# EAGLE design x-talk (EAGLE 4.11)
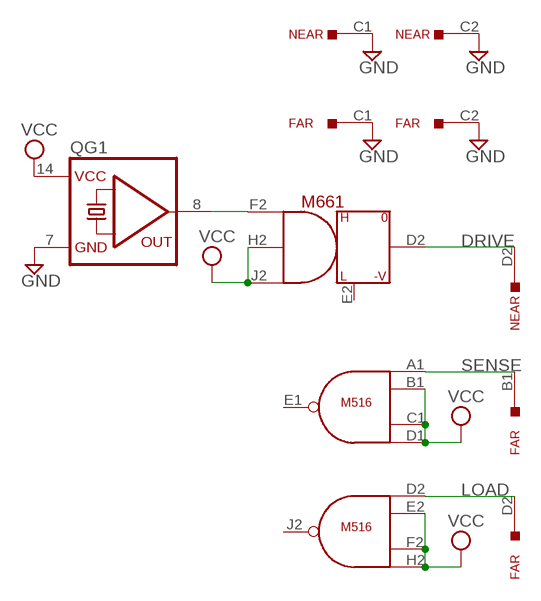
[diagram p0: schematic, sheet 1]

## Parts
FAR  M916  [H807]
M516  M117  [H807]
M661  M651  [H807]
NEAR  M916  [H807]
QG1  QG5860  [DIL14S]

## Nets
DRIVE: M661.D2(OUT) NEAR.D2
GND: FAR.C1 FAR.C2 NEAR.C1 NEAR.C2 QG1.7(GND)
LOAD: FAR.D2 M516.D2(IN1)
N$1: M661.F2(IN1) QG1.8(OUT)
SENSE: FAR.B1 M516.A1(IN1)
VCC: M516.B1(IN2) M516.C1(IN3) M516.D1(IN4) M516.E2(IN2) M516.F2(IN3) M516.H2(IN4) M661.H2(IN2) M661.J2(IN3) QG1.14(VCC)
Unconnected: FAR.A1 FAR.A2 FAR.B2 FAR.D1 FAR.E1 FAR.E2 FAR.F1 FAR.F2 FAR.H1 FAR.H2 FAR.J1 FAR.J2 FAR.K1 FAR.K2 FAR.L1 FAR.L2 FAR.M1 FAR.M2 FAR.N1 FAR.N2 FAR.P1 FAR.P2 FAR.R1 FAR.R2 FAR.S1 FAR.S2 FAR.T1 FAR.T2 FAR.U1 FAR.U2 FAR.V1 FAR.V2 M516.E1(OUT) M516.F1(IN1) M516.H1(IN2) M516.J1(IN3) M516.J2(OUT) M516.K1(IN4) M516.K2(IN1) M516.L1(OUT) M516.L2(IN2) M516.M1(IN1) M516.M2(IN3) M516.N1(IN2) M516.N2(IN4) M516.P1(IN3) M516.P2(OUT) M516.R1(IN4) M516.R2(IN1) M516.S1(OUT) M516.S2(IN2) M516.T2(IN3) M516.U1 M516.U2(IN4) M516.V1 M516.V2(OUT) M661.E2(SLOW) M661.K2(OUT) M661.L2(SLOW) M661.M2(IN1) M661.N2(IN2) M661.P2(IN3) M661.R2(SLOW) M661.S2(OUT) M661.T2(IN1) M661.U2(IN2) M661.V2(IN3) NEAR.A1 NEAR.A2 NEAR.B1 NEAR.B2 NEAR.D1 NEAR.E1 NEAR.E2 NEAR.F1 NEAR.F2 NEAR.H1 NEAR.H2 NEAR.J1 NEAR.J2 NEAR.K1 NEAR.K2 NEAR.L1 NEAR.L2 NEAR.M1 NEAR.M2 NEAR.N1 NEAR.N2 NEAR.P1 NEAR.P2 NEAR.R1 NEAR.R2 NEAR.S1 NEAR.S2 NEAR.T1 NEAR.T2 NEAR.U1 NEAR.U2 NEAR.V1 NEAR.V2

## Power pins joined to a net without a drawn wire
-15V: M661.B2(-15V)
GND: M516.C2(GND) M516.T1(GND) M661.C2(GND)
VCC: M516.A2(VCC) M661.A2(VCC)

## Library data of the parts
FAR NEAR = dec-m:M916: Simple 36 pin connector/wire cable
M516 = dec-m:M117: 6 4-input NAND Gates
M661 = dec-m:M651: M651 - Negative Output Converter
QG1 = crystal:QG5860: CRYSTAL RESONATOR

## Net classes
0 default: width 0.508 mm

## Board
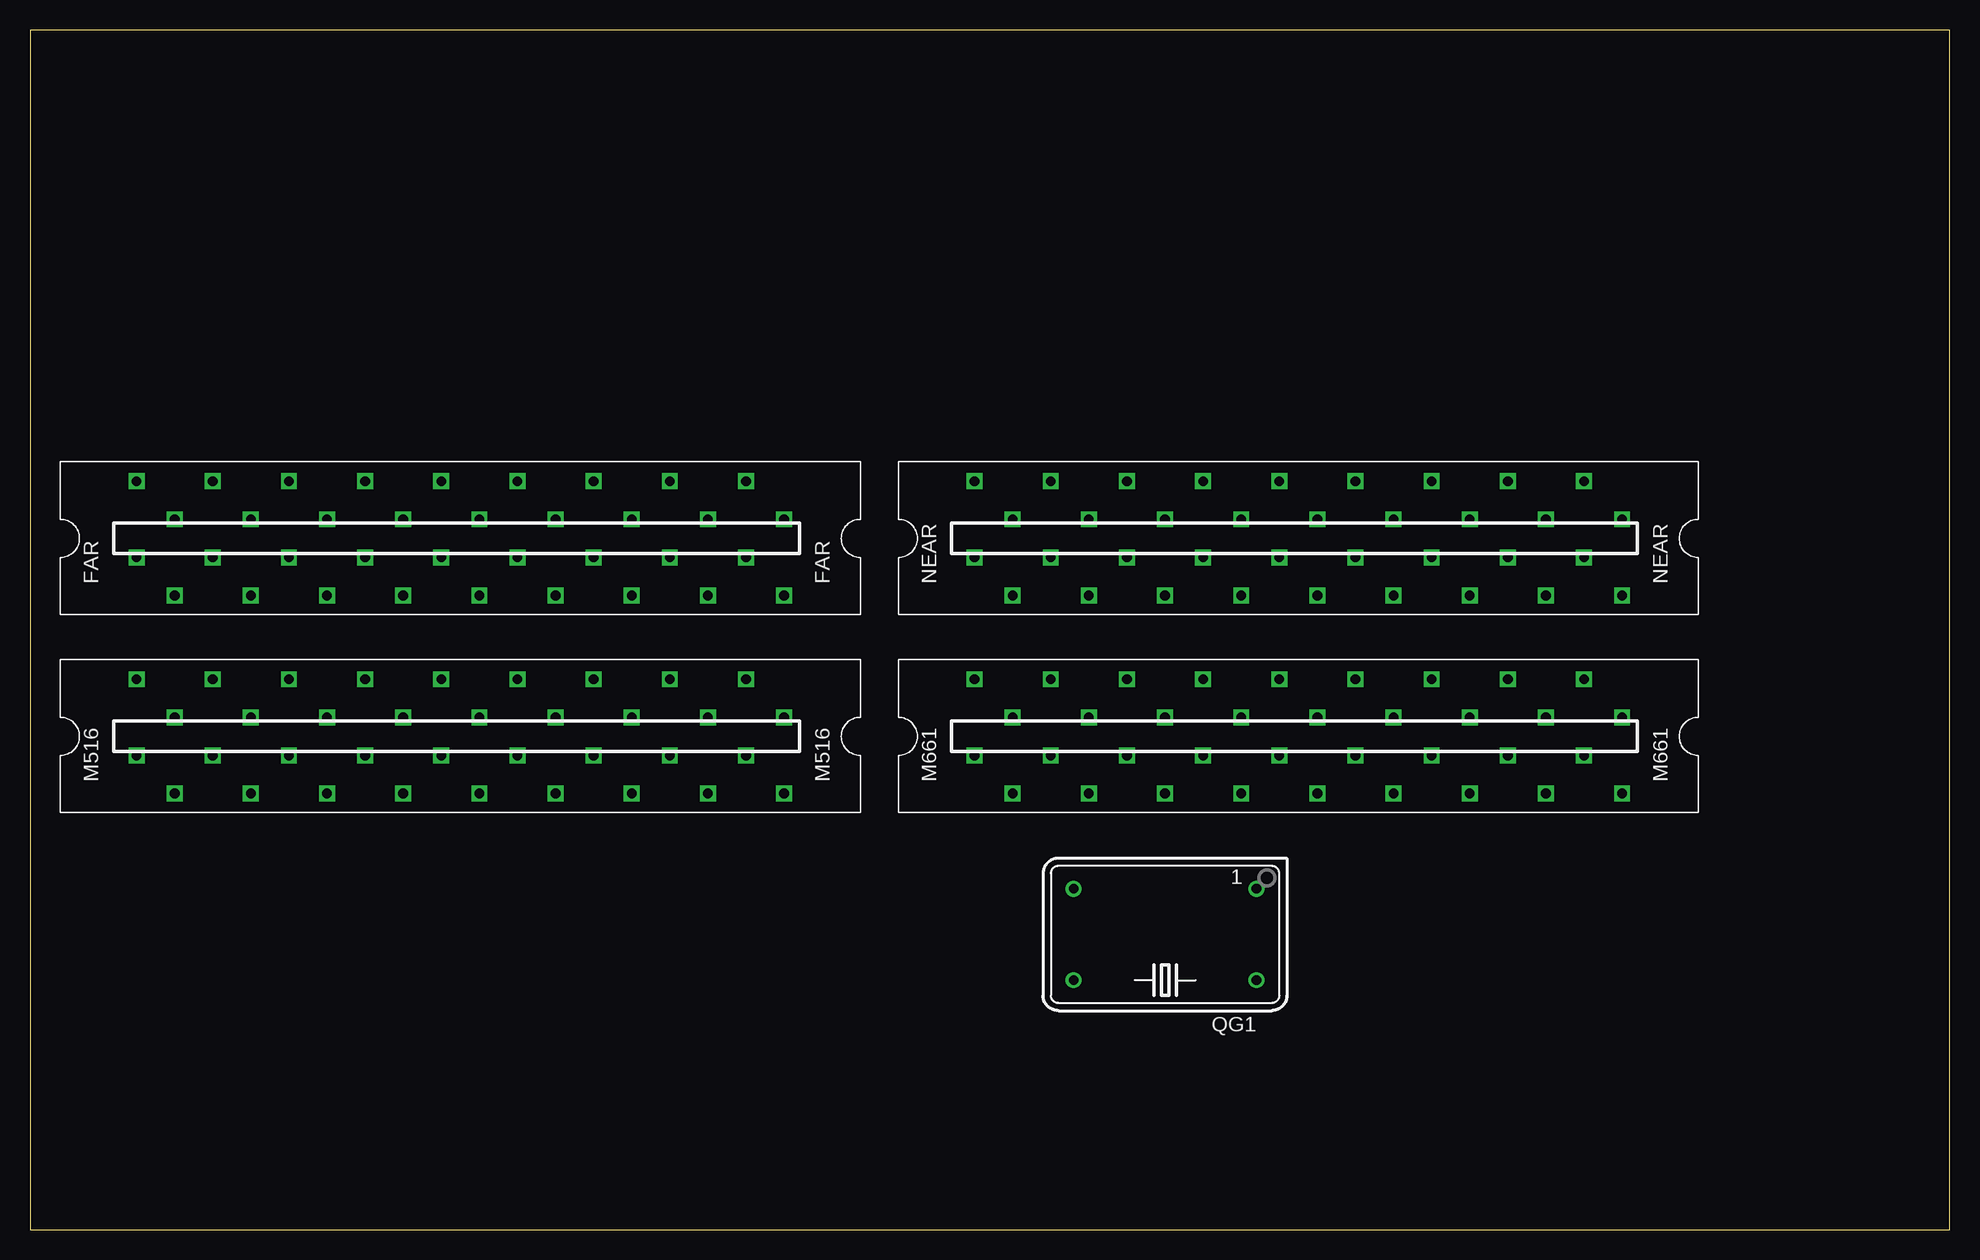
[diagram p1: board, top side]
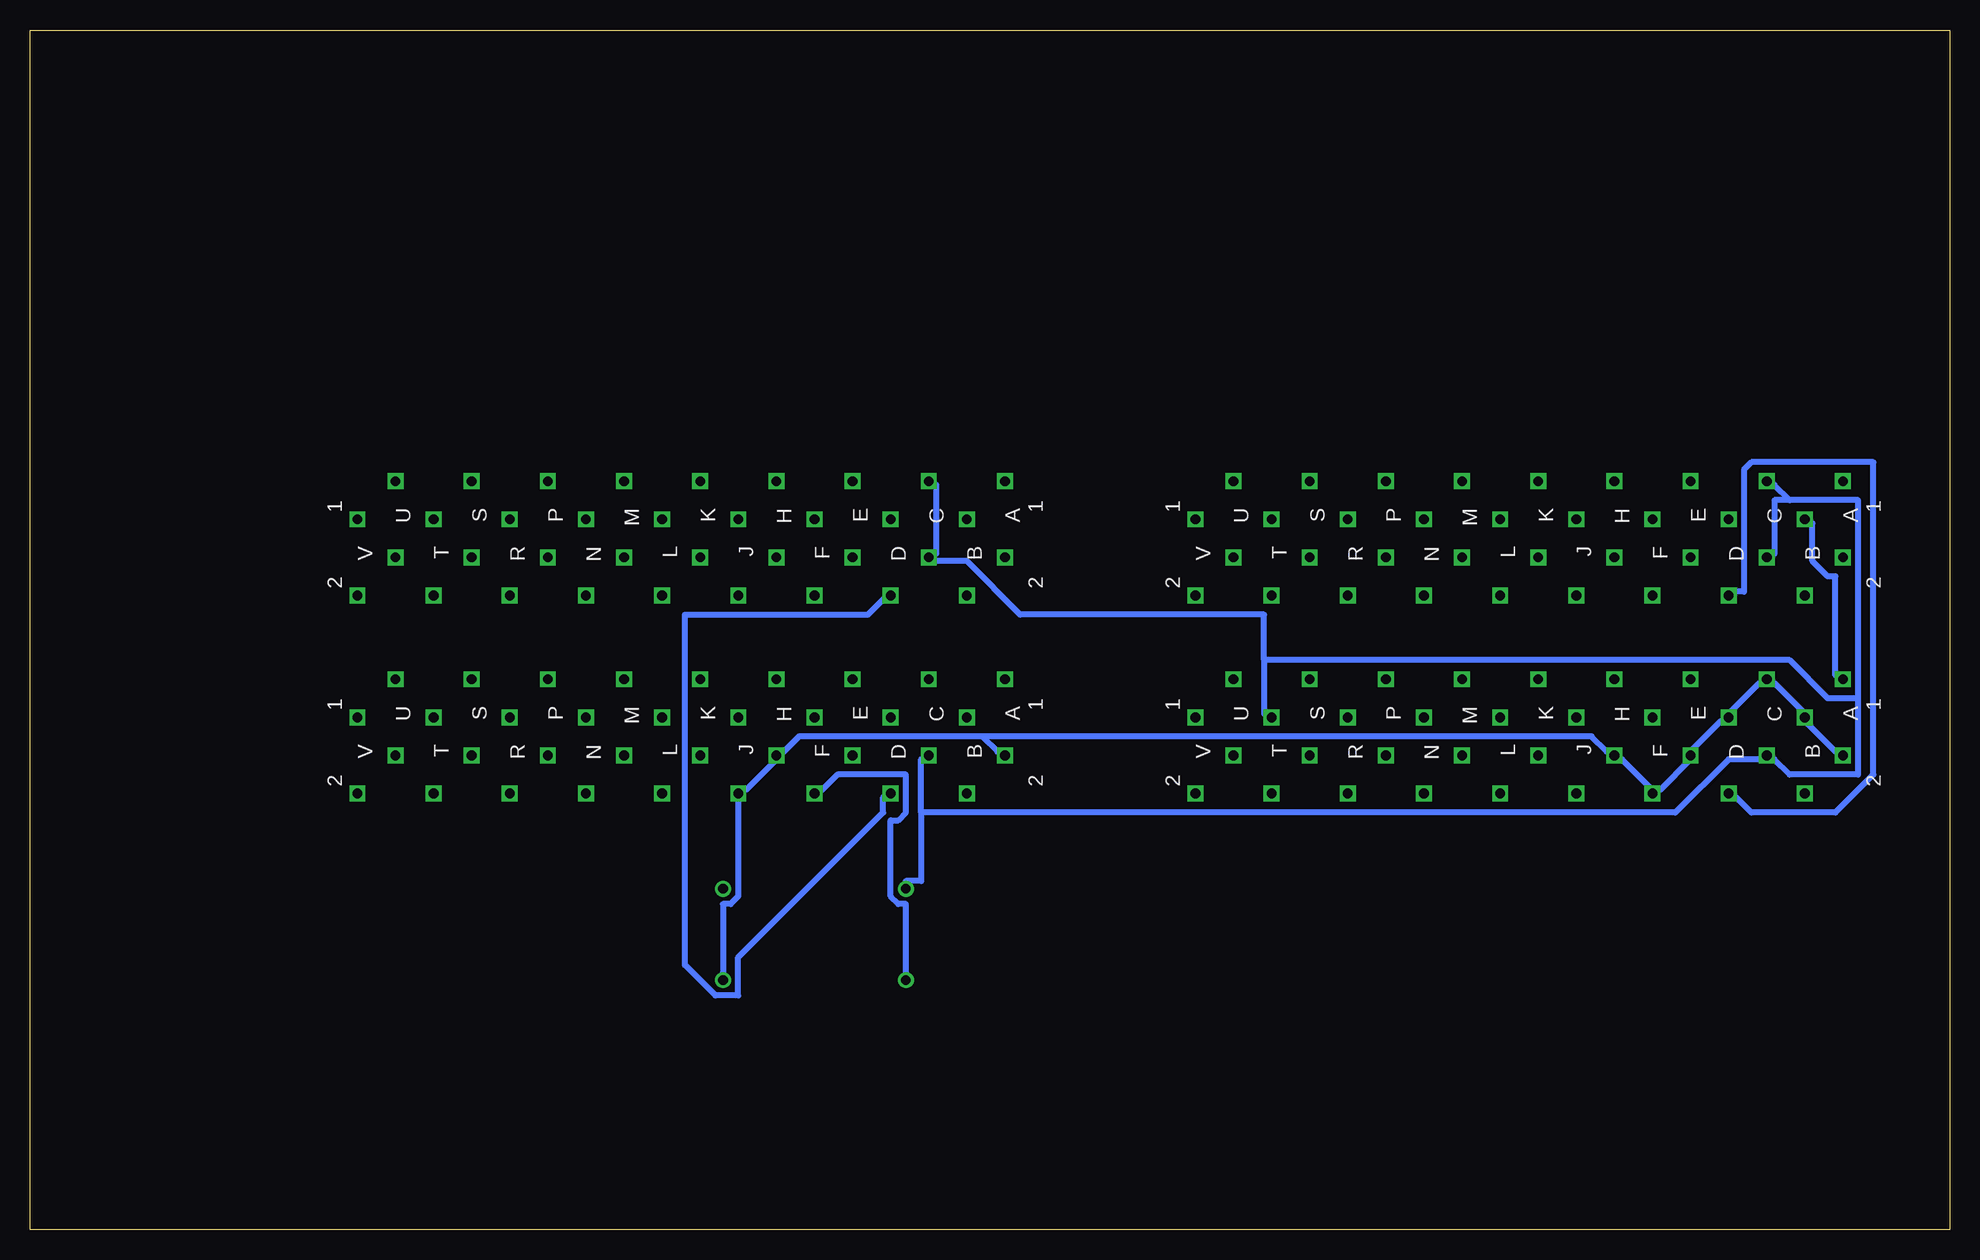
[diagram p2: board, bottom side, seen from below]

Size 160 x 100 mm. Coordinates in mm from the lower left corner, seen from the top.
Outline: 0,0 160,0 160,100 0,100 0,0
Copper layers (1*16): Top 0.035mm / dielectric 1.5mm / Bottom 0.035mm
Design rules "default": minimum track width 10mil, minimum drill 24mil, track to track 8mil, track to pad 8mil, pad to pad 8mil, via to via 8mil, smd to smd 8mil, copper to edge 40mil, drill to drill 8mil, minimum pad ring 10mil, minimum via ring 8mil, stop-mask expansion 4mil, vias tented up to drill 0mil, thermal gap 10mil

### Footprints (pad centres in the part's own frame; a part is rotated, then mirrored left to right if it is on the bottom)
H807 = drill 0.813 square: A1 4.763,28.575; A2 -1.587,28.575; B1 1.587,25.4; B2 -4.763,25.4; C1 4.763,22.225; C2 -1.587,22.225; D1 1.587,19.05; D2 -4.763,19.05; E1 4.763,15.875; E2 -1.587,15.875; F1 1.587,12.7; F2 -4.763,12.7; H1 4.763,9.525; H2 -1.587,9.525; J1 1.587,6.35; J2 -4.763,6.35; K1 4.763,3.175; K2 -1.587,3.175; L1 1.587,0; L2 -4.763,0; M1 4.763,-3.175; M2 -1.587,-3.175; N1 1.587,-6.35; N2 -4.763,-6.35; P1 4.763,-9.525; P2 -1.587,-9.525; R1 1.587,-12.7; R2 -4.763,-12.7; S1 4.763,-15.875; S2 -1.587,-15.875; T1 1.587,-19.05; T2 -4.763,-19.05; U1 4.763,-22.225; U2 -1.587,-22.225; V1 1.587,-25.4; V2 -4.763,-25.4
DIL14S = drill 0.813 round: 1 -7.62,-3.81; 7 7.62,-3.81; 8 7.62,3.81; 14 -7.62,3.81

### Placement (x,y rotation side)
FAR  37.46,57.62 90 top
M516  37.46,41.11 90 top
M661  107.31,41.11 90 top
NEAR  107.31,57.62 90 top
QG1  94.61,24.6 180 top

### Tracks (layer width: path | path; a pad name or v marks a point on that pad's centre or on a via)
DRIVE
  Bottom 0.508: M661.D2 88.89,36.03 88.89,34.76 100.96,22.7 100.96,19.52 102.86,19.52 105.41,22.06 105.41,51.27 90.16,51.27 88.89,52.54 NEAR.D2
GND
  Bottom 0.508: 57.15,47.46 57.15,51.27 77.46,51.27 81.91,55.71 84.45,55.71 NEAR.C2 84.45,56.35 84.45,62.06 NEAR.C1 | 57.15,47.46 57.15,43.02 M516.T1 | 85.72,34.76 85.72,29.04 86.99,29.04 QG1.7 | 85.72,34.76 85.72,39.2 M661.C2 | 7.62,44.28 7.62,60.8 13.33,60.8 | 7.62,44.28 7.62,37.94 13.33,37.94 14.6,39.2 M516.C2 15.87,39.2 18.41,39.2 22.86,34.76 85.72,34.76 | 13.33,60.8 14.6,62.06 FAR.C1 | 13.33,60.8 14.6,60.8 14.6,56.35 FAR.C2 | 57.15,47.46 13.33,47.46 10.16,44.28 7.62,44.28
LOAD
  Bottom 0.508: M516.D2 17.77,36.03 16.5,34.76 9.52,34.76 6.34,37.94 6.34,63.97 16.5,63.97 17.14,63.34 17.14,53.17 17.77,53.17 FAR.D2
N$1
  Bottom 0.508: QG1.8 86.99,21.42 86.99,27.14 87.62,27.14 88.26,27.77 88.26,34.12 87.62,34.12 86.99,34.76 86.99,37.94 92.7,37.94 93.97,36.66 M661.F2
SENSE
  Bottom 0.508: M516.A1 9.52,46.19 9.52,54.45 10.16,54.45 11.43,55.71 11.43,58.89 FAR.B1
VCC
  Bottom 0.508: M516.A2 9.52,39.84 12.06,42.38 M516.B1 12.06,43.02 14.6,45.55 M516.C1 15.87,45.55 18.41,43.02 M516.D1 19.04,42.38 21.58,39.84 M516.E2 21.58,39.2 24.12,36.66 M516.F2 24.76,36.66 27.3,39.2 M516.H2 28.57,39.84 29.84,41.11 80.64,41.11 | 80.64,41.11 79.37,39.84 M661.A2 | 80.64,41.11 95.88,41.11 97.15,39.84 M661.H2 97.78,39.2 100.32,36.66 M661.J2 100.96,36.03 100.96,27.77 101.59,27.14 102.23,27.14 102.23,21.42 QG1.14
